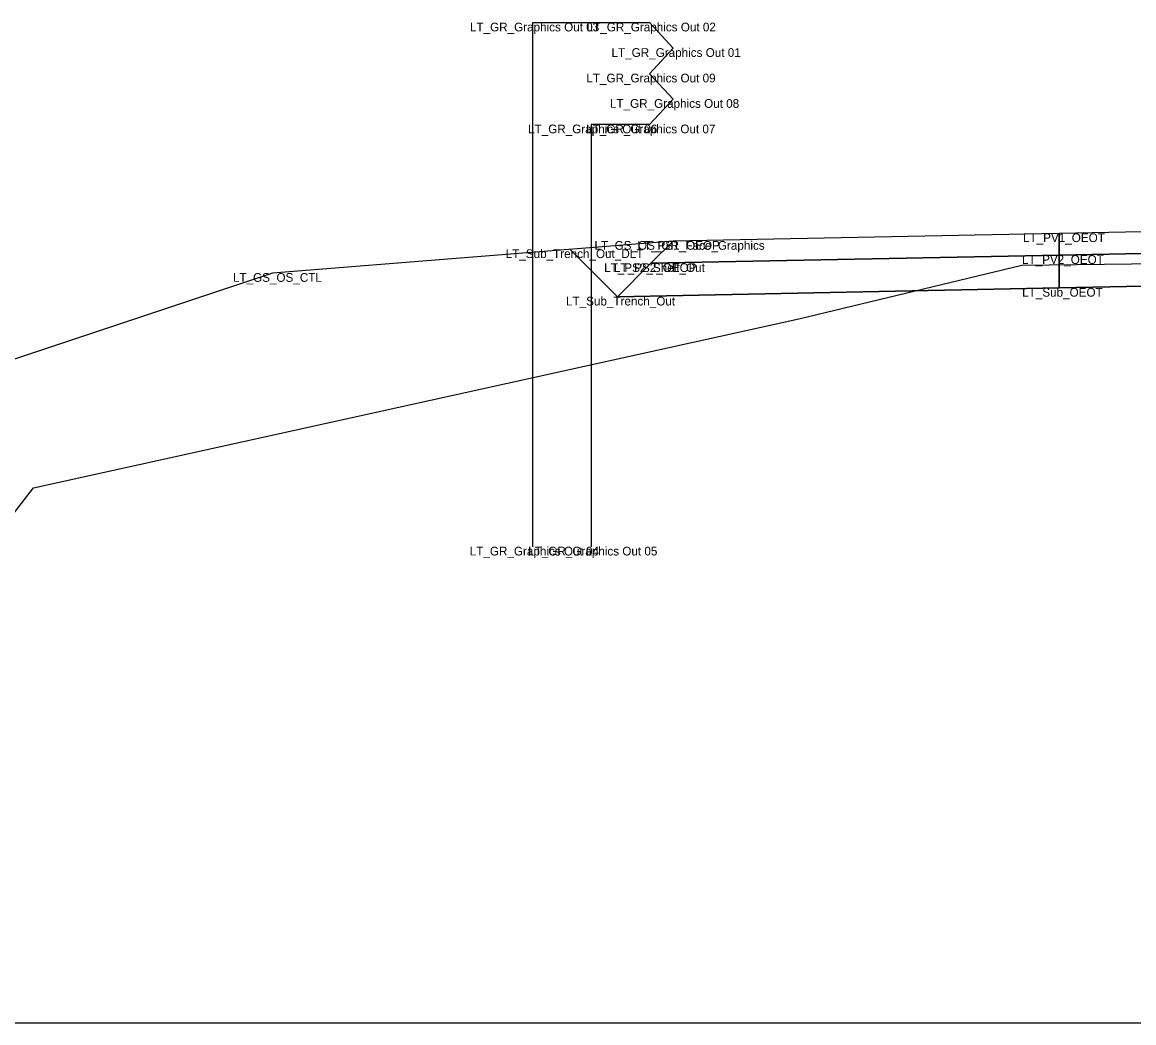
# Model space of a CAD drawing. Extents: x -26 to 203, y -10 to 20020.
# Drawn here: x 77.13 to 89.85, y 16000 to 16011.46 of the extents above; entities that cross this region are included whole.
import ezdxf

# ---------------------------------------------------------------- set-up
doc = ezdxf.new("R2010")
doc.units = 0
for name, color, linetype in [('Default', 7, 'Continuous'), ('Exist Cross Section Cell', 7, 'Continuous'), ('Exist XS Ground Line', 7, 'Continuous'), ('Prop CMT Guardrail Graphics', 7, 'Continuous'), ('Prop CMT Pvmt Course 1', 7, 'Continuous'), ('Prop CMT Pvmt Course 2', 7, 'Continuous'), ('Prop CMT Pvmt Surface', 7, 'Continuous'), ('Prop CMT Pvmt Surface Shoulder', 7, 'Continuous'), ('Prop CMT Shld Paved Course 1', 7, 'Continuous'), ('Prop CMT Shld Paved Course 2', 7, 'Continuous'), ('Prop CMT Slope Grass', 7, 'Continuous'), ('Prop CMT Subgrade Earthwork', 7, 'Continuous')]:
    doc.layers.add(name, color=color, linetype=linetype)

msp = doc.modelspace()

# ---------------------------------------------------------------- linework, layer by layer
at = {"layer": 'Exist Cross Section Cell'}
msp.add_line((0, 16000), (100, 16000), dxfattribs=at)
at = {"layer": 'Exist XS Ground Line'}
for p, q in [((86.023, 16008.06), (88.574, 16008.673)), ((88.574, 16008.673), (90.365, 16008.695)), ((77.265, 16006.124), (86.023, 16008.06)), ((74.061, 16002.012), (77.265, 16006.124))]:
    msp.add_line(p, q, dxfattribs=at)
at = {"layer": 'Prop CMT Guardrail Graphics'}
for points in [[(82.979, 16005.45), (82.979, 16011.45)], [(82.979, 16011.45), (84.312, 16011.45), (84.583, 16011.158)], [(84.583, 16011.158), (84.312, 16010.866)], [(84.312, 16010.866), (84.583, 16010.575)], [(84.583, 16010.575), (84.313, 16010.283), (83.646, 16010.283)], [(83.646, 16010.283), (83.646, 16005.45)]]:
    msp.add_lwpolyline(points, dxfattribs=at)
at = {"layer": 'Prop CMT Pvmt Course 1'}
for points in [[(100, 16009.258), (89, 16009.038)], [(89, 16009.038), (89, 16008.788)], [(89, 16008.788), (100, 16009.008)]]:
    msp.add_lwpolyline(points, dxfattribs=at)
at = {"layer": 'Prop CMT Pvmt Course 2'}
for points in [[(100, 16009.008), (89, 16008.788)], [(89, 16008.788), (89, 16008.413)], [(89, 16008.413), (100, 16008.633)]]:
    msp.add_lwpolyline(points, dxfattribs=at)
at = {"layer": 'Prop CMT Pvmt Surface'}
msp.add_lwpolyline([(100, 16009.258), (89, 16009.038)], dxfattribs=at)
at = {"layer": 'Prop CMT Pvmt Surface Shoulder'}
msp.add_lwpolyline([(89, 16009.038), (84.583, 16008.95)], dxfattribs=at)
at = {"layer": 'Prop CMT Shld Paved Course 1'}
for points in [[(89, 16009.038), (84.583, 16008.95), (84.328, 16008.695)], [(89, 16008.788), (89, 16009.038)], [(84.328, 16008.695), (89, 16008.788)]]:
    msp.add_lwpolyline(points, dxfattribs=at)
at = {"layer": 'Prop CMT Shld Paved Course 2'}
for points in [[(89, 16008.788), (84.328, 16008.695)], [(89, 16008.413), (89, 16008.788)], [(84.328, 16008.695), (83.946, 16008.312)], [(84.328, 16008.695), (84.328, 16008.695)], [(83.946, 16008.312), (89, 16008.413)]]:
    msp.add_lwpolyline(points, dxfattribs=at)
at = {"layer": 'Prop CMT Slope Grass'}
for points in [[(84.583, 16008.95), (80, 16008.583)], [(84.583, 16008.95), (84.583, 16008.95)], [(80, 16008.583), (69.25, 16005)]]:
    msp.add_lwpolyline(points, dxfattribs=at)
at = {"layer": 'Prop CMT Subgrade Earthwork'}
for points in [[(83.946, 16008.312), (83.402, 16008.855)], [(100, 16008.633), (89, 16008.413)], [(89, 16008.413), (83.946, 16008.312)]]:
    msp.add_lwpolyline(points, dxfattribs=at)

# ---------------------------------------------------------------- texts
at = {"layer": 'Default'}
for s, p in [('LT_GR_Graphics Out 03', (82.258, 16011.35)), ('LT_GR_Graphics Out 02', (83.593, 16011.35)), ('LT_GR_Graphics Out 01', (83.878, 16011.058)), ('LT_GR_Graphics Out 09', (83.59, 16010.766)), ('LT_GR_Graphics Out 08', (83.86, 16010.475)), ('LT_GR_Graphics Out 06', (82.923, 16010.183)), ('LT_GR_Graphics Out 07', (83.588, 16010.183)), ('LT_PV1_OEOT', (88.587, 16008.938)), ('LT_GS_OS_GR_Face_Graphics', (83.683, 16008.85)), ('LT_PS1_OEOP', (84.174, 16008.85)), ('LT_Sub_Trench_Out_DLT', (82.667, 16008.755)), ('LT_PV2_OEOT', (88.575, 16008.688)), ('LT_PS2_Shelf_Out', (83.794, 16008.595)), ('LT_PS2_OEOP', (83.907, 16008.595)), ('LT_GS_OS_CTL', (79.546, 16008.483)), ('LT_Sub_OEOT', (88.577, 16008.313)), ('LT_Sub_Trench_Out', (83.357, 16008.212)), ('LT_GR_Graphics Out 04', (82.256, 16005.35)), ('LT_GR_Graphics Out 05', (82.924, 16005.35))]:
    msp.add_text(s, height=0.1, dxfattribs=at).set_placement(p)

doc.saveas('drawing.dxf')
